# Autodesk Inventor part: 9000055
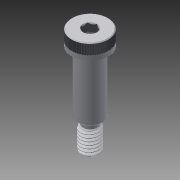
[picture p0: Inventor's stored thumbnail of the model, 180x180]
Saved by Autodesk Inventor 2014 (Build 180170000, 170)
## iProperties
Company: NHTSA/VRTC
Created: 2012-08
Material: Generic
Document SubType Name: Modeling
Designer: Mike Vanvoorhis
Density: 1 g/cm^3
Description: SCREW, SHSS 1/2" x 1 1/4"
Project: CHILD SIDE IMPACT SLED
Part Number: 9000055
Appearance: Default
Translation Standard: IGES 5.3
FileName: C:\SW Working Folder\Fixes\91259A714.igs
PreProcessor: SolidWorks 2009
PostProcessor: Build: 160, Release: 2012 RTM - Date: Tue 03/01/2011
Sent Units: inch
Uncertainty: 1e-08
Author: Dave Walker
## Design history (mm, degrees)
node "91259A714.IGS1"
feature "Composite1"
body "Srf1"
